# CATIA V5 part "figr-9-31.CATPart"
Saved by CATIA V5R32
Part number: Part1
Bounding box of the stored display mesh (mm): x -60 to 60, y -41.231 to 41.231, z -41.231 to 41.231
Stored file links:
  D:\PROJECTS\Project 2022\CATIA V5 6R 2022\Resources\Part Files\c09_catia_v5_6r2022_prt\c09_catia_v5_6r2022_prt\figr-9-31.CATPart
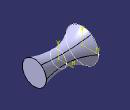
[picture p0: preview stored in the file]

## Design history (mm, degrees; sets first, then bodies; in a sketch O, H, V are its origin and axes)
Body1 (main body)
  Sketch1 on yz-plane, origin (0, 0, 0), H (0, 1, 0), V (0, 0, 1)
    circle A1 centre (0, 0) radius 20
  Plane1: type Offset, RefPlane yz-plane, Offset 60
  Plane2: type Offset, RefPlane yz-plane, Offset -60
  Sketch2 on Plane1, origin (60, 0, 0), H (0, 1, 0), V (0, 0, 1)
    circle A1 centre (0, 0) radius 30
  Sketch3 on Plane2, origin (-60, 0, 0), H (0, 1, 0), V (0, 0, 1)
    circle A1 centre (0, 0) radius 41.2311
  Loft1: solid, Sections (Sketch2; Sketch1; Sketch3)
